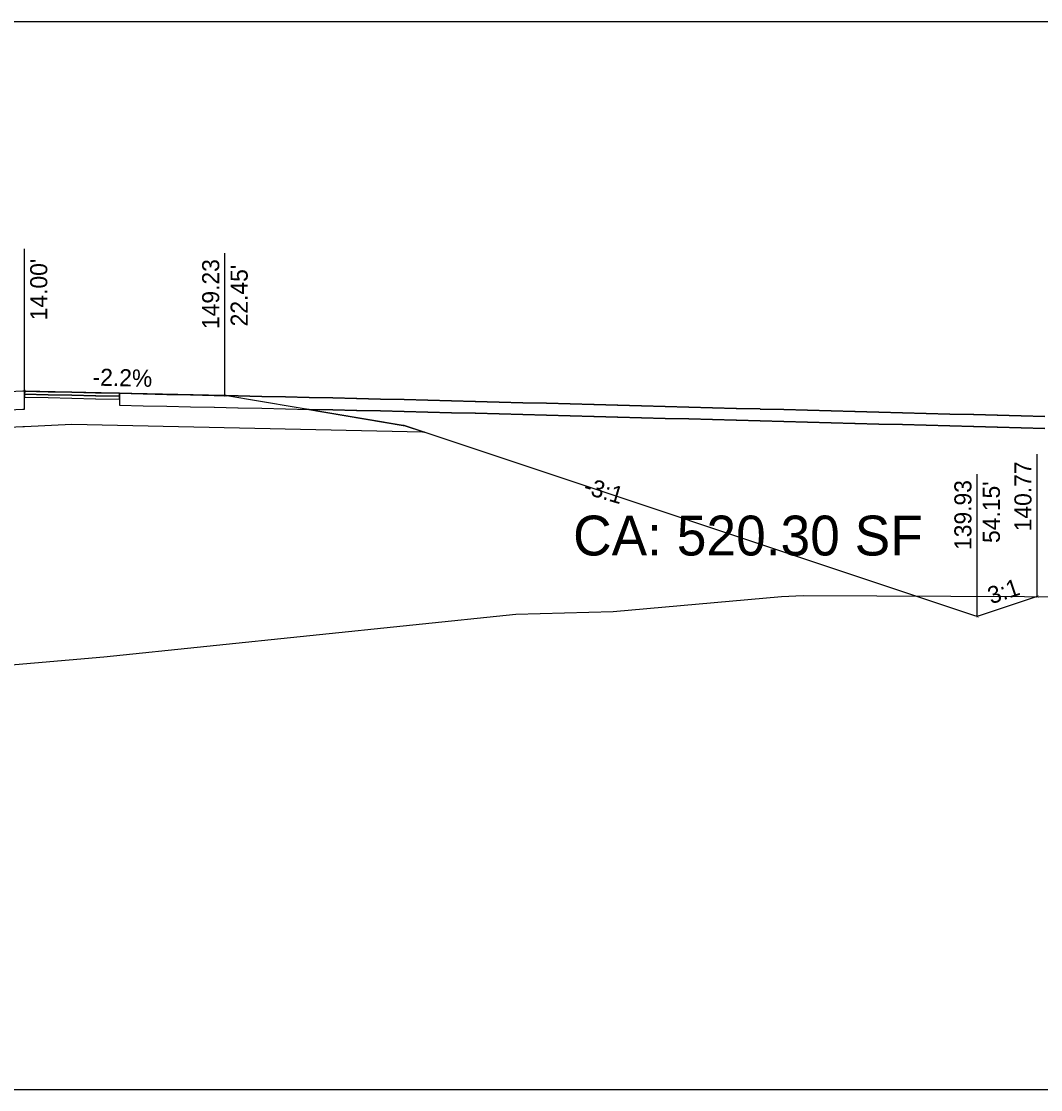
# Model space of a CAD drawing. Extents: x -26 to 4403, y -13 to 9578.
# Drawn here: x 1263.87 to 1306.82, y 7000 to 7045 of the extents above; entities that cross this region are included whole.
import ezdxf

# ---------------------------------------------------------------- set-up
doc = ezdxf.new("R2010")
doc.units = 0
for name, color, linetype in [('_CIVIL_CONSTRUCTION', 7, 'Continuous'), ('CONST_DCH', 7, 'Continuous'), ('CONST_LV3', 7, 'Continuous'), ('DTM_CORRIDOR', 7, 'Continuous'), ('DTM_P_FINISHED_GRADE', 7, 'Continuous'), ('DTM_TEMP_DROP', 7, 'Continuous'), ('DTM_X_GROUND', 7, 'Continuous'), ('XS_CELL', 7, 'Continuous'), ('XS_M_SHAPES_EARTHWORK', 7, 'Continuous'), ('XS_P_ASPHALT', 7, 'Continuous'), ('XS_P_DR_ASPHALT', 7, 'Continuous'), ('XS_P_DR_ASPHALT_B', 7, 'Continuous'), ('XS_P_DR_GRAVEL', 7, 'Continuous'), ('XS_P_GROUND', 7, 'Continuous'), ('XS_P_SHOULDER', 7, 'Continuous'), ('XS_P_SUBGRADE_GRANULAR', 7, 'Continuous'), ('XS_P_TX_CLEARZONE', 7, 'Continuous'), ('XS_P_TX_FS_BS', 7, 'Continuous'), ('XS_SHEET_EW_TX_AREA', 7, 'Continuous')]:
    doc.layers.add(name, color=color, linetype=linetype)

msp = doc.modelspace()

# ---------------------------------------------------------------- linework, layer by layer
at = {"layer": 'CONST_LV3'}
msp.add_lwpolyline([(1264, 7029.421), (1264.996, 7029.399), (1265.996, 7029.377), (1266.996, 7029.355), (1267.996, 7029.333), (1268.996, 7029.311), (1269.996, 7029.289), (1270.996, 7029.267), (1271.996, 7029.245), (1272.996, 7029.223), (1273.996, 7029.201), (1274.996, 7029.179), (1275.996, 7029.157), (1276.996, 7029.135), (1277.996, 7029.113), (1278.996, 7029.091), (1279.996, 7029.069), (1280, 7029.069), (1280.996, 7029.042), (1281.996, 7029.016), (1282.996, 7028.989), (1283.996, 7028.963), (1284.996, 7028.936), (1285.996, 7028.91), (1286.996, 7028.883), (1287.996, 7028.857), (1288.996, 7028.83), (1289.996, 7028.804), (1290.996, 7028.777), (1291.996, 7028.751), (1292.996, 7028.725), (1293.996, 7028.698), (1294.996, 7028.672), (1295.996, 7028.645), (1296.996, 7028.619), (1297.996, 7028.592), (1298.996, 7028.566), (1299.996, 7028.539), (1300.996, 7028.513), (1301.996, 7028.486), (1302.996, 7028.46), (1303.996, 7028.433), (1304.996, 7028.407), (1305.996, 7028.38), (1306.996, 7028.354)], dxfattribs=at)
at = {"layer": 'DTM_P_FINISHED_GRADE'}
for points in [[(1264, 7029.421), (1264.996, 7029.399), (1265, 7029.399), (1265.996, 7029.377), (1266, 7029.377), (1266.996, 7029.355), (1267, 7029.355), (1267.996, 7029.333), (1268, 7029.333)], [(1268, 7029.333), (1268, 7029.333), (1268.996, 7029.311), (1269, 7029.311), (1269.996, 7029.289), (1270, 7029.289), (1270.996, 7029.267), (1271, 7029.267), (1271.996, 7029.245), (1272, 7029.245), (1272.996, 7029.223), (1273, 7029.223), (1273.996, 7029.201), (1274, 7029.201), (1274.996, 7029.179), (1275, 7029.179), (1275.996, 7029.157), (1276, 7029.157), (1276.996, 7029.135), (1277, 7029.135), (1277.996, 7029.113), (1278, 7029.113), (1278.996, 7029.091), (1279, 7029.091), (1279.996, 7029.069), (1280, 7029.069), (1280.996, 7029.042), (1281, 7029.042), (1281.996, 7029.016), (1282, 7029.016), (1282.996, 7028.989), (1283, 7028.989), (1283.996, 7028.963), (1284, 7028.963), (1284.996, 7028.936), (1285, 7028.936), (1285.996, 7028.91), (1286, 7028.91), (1286.996, 7028.883), (1287, 7028.883), (1287.996, 7028.857), (1288, 7028.857), (1288.996, 7028.83), (1289, 7028.83), (1289.996, 7028.804), (1290, 7028.804), (1290.996, 7028.777), (1291, 7028.777), (1291.996, 7028.751), (1292, 7028.751), (1292.996, 7028.725), (1293, 7028.724), (1293.996, 7028.698), (1294, 7028.698), (1294.996, 7028.672), (1295, 7028.671), (1295.996, 7028.645), (1296, 7028.645), (1296.996, 7028.619), (1297, 7028.619), (1297.996, 7028.592), (1298, 7028.592), (1298.996, 7028.566), (1299, 7028.566), (1299.996, 7028.539), (1300, 7028.539), (1300.996, 7028.513), (1301, 7028.513), (1301.996, 7028.486), (1302, 7028.486), (1302.996, 7028.46), (1303, 7028.46), (1303.996, 7028.433), (1304, 7028.433), (1304.996, 7028.407), (1305, 7028.407), (1305.996, 7028.38), (1306, 7028.38), (1306.996, 7028.354)]]:
    msp.add_lwpolyline(points, dxfattribs=at)
at = {"layer": 'DTM_X_GROUND'}
msp.add_lwpolyline([(1172.393, 7016.843), (1201.803, 7015.398), (1214.564, 7014.215), (1224.971, 7013.522), (1232.816, 7013.949), (1243.916, 7015.546), (1247.514, 7017.177), (1252.067, 7016.906), (1267.338, 7018.231), (1284.701, 7020.032), (1288.812, 7020.146), (1295.897, 7020.771), (1296.81, 7020.815), (1306.145, 7020.771), (1331.242, 7020.749), (1362.053, 7020.566), (1388.429, 7020.524), (1400, 7020.43)], dxfattribs=at)
at = {"layer": 'XS_CELL'}
msp.add_line((1250, 7000), (1400, 7000), dxfattribs=at)
at = {"layer": 'XS_M_SHAPES_EARTHWORK'}
for points in [[(1306.996, 7027.854), (1306, 7027.88), (1305.996, 7027.88), (1305, 7027.907), (1304.996, 7027.907), (1304, 7027.933), (1303.996, 7027.933), (1303, 7027.96), (1302.996, 7027.96), (1302, 7027.986), (1301.996, 7027.986), (1301, 7028.013), (1300.996, 7028.013), (1300, 7028.039), (1299.996, 7028.039), (1299, 7028.066), (1298.996, 7028.066), (1298, 7028.092), (1297.996, 7028.092), (1297, 7028.119), (1296.996, 7028.119), (1296, 7028.145), (1295.996, 7028.145), (1295, 7028.171), (1294.996, 7028.172), (1294, 7028.198), (1293.996, 7028.198), (1293, 7028.224), (1292.996, 7028.225), (1292, 7028.251), (1291.996, 7028.251), (1291, 7028.277), (1290.996, 7028.277), (1290, 7028.304), (1289.996, 7028.304), (1289, 7028.33), (1288.996, 7028.33), (1288, 7028.357), (1287.996, 7028.357), (1287, 7028.383), (1286.996, 7028.383), (1286, 7028.41), (1285.996, 7028.41), (1285, 7028.436), (1284.996, 7028.436), (1284, 7028.463), (1283.996, 7028.463), (1283, 7028.489), (1282.996, 7028.489), (1282, 7028.516), (1281.996, 7028.516), (1281, 7028.542), (1280.996, 7028.542), (1280, 7028.569), (1279.996, 7028.569), (1279, 7028.591), (1278.996, 7028.591), (1278, 7028.613), (1277.996, 7028.613), (1277, 7028.635), (1276.996, 7028.635), (1276, 7028.657), (1275.996, 7028.657), (1275.901, 7028.659), (1279.961, 7027.982), (1280, 7027.976), (1280.857, 7027.69), (1280.775, 7027.692), (1266, 7028.017), (1265.989, 7028.016), (1264, 7027.921), (1263.924, 7027.917), (1250, 7027.249)], [(1252.067, 7016.906), (1267.338, 7018.231), (1284.701, 7020.032), (1288.812, 7020.146), (1295.897, 7020.771), (1296.81, 7020.815), (1306.145, 7020.771), (1331.242, 7020.749), (1362.053, 7020.566)]]:
    msp.add_lwpolyline(points, dxfattribs=at)
at = {"layer": 'XS_P_ASPHALT'}
msp.add_lwpolyline([(1249.924, 7028.745), (1236, 7028.077), (1236, 7028.073), (1236, 7027.327), (1249.924, 7027.995), (1250, 7027.999), (1263.924, 7028.667), (1264, 7028.671), (1264, 7029.417), (1264, 7029.421), (1263.924, 7029.417), (1250, 7028.749), (1249.924, 7028.745)], dxfattribs=at)
at = {"layer": 'XS_P_DR_ASPHALT'}
msp.add_lwpolyline([(1264, 7029.421), (1264, 7029.296), (1264.996, 7029.274), (1264.996, 7029.274), (1265, 7029.274), (1265.996, 7029.252), (1266, 7029.252), (1266, 7029.252), (1266, 7029.252), (1266.996, 7029.23), (1267, 7029.23), (1267.996, 7029.208), (1268, 7029.208), (1268, 7029.333), (1267.996, 7029.333), (1267, 7029.355), (1266.996, 7029.355), (1266, 7029.377), (1266, 7029.377), (1266, 7029.377), (1265.996, 7029.377), (1265, 7029.399), (1264.996, 7029.399), (1264.996, 7029.399), (1264, 7029.421)], dxfattribs=at)
at = {"layer": 'XS_P_DR_ASPHALT_B'}
msp.add_lwpolyline([(1264, 7029.296), (1264, 7029.171), (1264.996, 7029.149), (1264.996, 7029.149), (1265, 7029.149), (1265.996, 7029.127), (1266, 7029.127), (1266, 7029.127), (1266, 7029.127), (1266.996, 7029.105), (1267, 7029.105), (1267.996, 7029.083), (1268, 7029.083), (1268, 7029.208), (1267.996, 7029.208), (1267, 7029.23), (1266.996, 7029.23), (1266, 7029.252), (1266, 7029.252), (1266, 7029.252), (1265.996, 7029.252), (1265, 7029.274), (1264.996, 7029.274), (1264.996, 7029.274), (1264, 7029.296)], dxfattribs=at)
at = {"layer": 'XS_P_DR_GRAVEL'}
for points in [[(1268, 7029.333), (1268, 7028.833), (1268.996, 7028.811), (1269, 7028.811), (1269.996, 7028.789), (1269.996, 7028.789), (1270, 7028.789), (1270.996, 7028.767), (1271, 7028.767), (1271.996, 7028.745), (1272, 7028.745), (1272, 7028.745), (1272.996, 7028.723), (1273, 7028.723), (1273.996, 7028.701), (1274, 7028.701), (1274.996, 7028.679), (1275, 7028.679), (1275.996, 7028.657), (1276, 7028.657), (1276.996, 7028.635), (1277, 7028.635), (1277.996, 7028.613), (1278, 7028.613), (1278.996, 7028.591), (1279, 7028.591), (1279.996, 7028.569), (1280, 7028.569), (1280.996, 7028.542), (1281, 7028.542), (1281.996, 7028.516), (1282, 7028.516), (1282.996, 7028.489), (1283, 7028.489), (1283.996, 7028.463), (1284, 7028.463), (1284.996, 7028.436), (1285, 7028.436), (1285.996, 7028.41), (1286, 7028.41), (1286.996, 7028.383), (1287, 7028.383), (1287.996, 7028.357), (1288, 7028.357), (1288.996, 7028.33), (1289, 7028.33), (1289.996, 7028.304), (1290, 7028.304), (1290.996, 7028.277), (1291, 7028.277), (1291.996, 7028.251), (1292, 7028.251), (1292.996, 7028.225), (1293, 7028.224), (1293.996, 7028.198), (1294, 7028.198), (1294.996, 7028.172), (1295, 7028.171), (1295.996, 7028.145), (1296, 7028.145), (1296.996, 7028.119), (1297, 7028.119), (1297.996, 7028.092), (1298, 7028.092), (1298.996, 7028.066), (1299, 7028.066), (1299.996, 7028.039), (1300, 7028.039), (1300.996, 7028.013), (1301, 7028.013), (1301.996, 7027.986), (1302, 7027.986), (1302.996, 7027.96), (1303, 7027.96), (1303.996, 7027.933), (1304, 7027.933), (1304.996, 7027.907), (1305, 7027.907), (1305.996, 7027.88), (1306, 7027.88), (1306.996, 7027.854)], [(1306.996, 7028.354), (1306, 7028.38), (1305.996, 7028.38), (1305, 7028.407), (1304.996, 7028.407), (1304, 7028.433), (1303.996, 7028.433), (1303, 7028.46), (1302.996, 7028.46), (1302, 7028.486), (1301.996, 7028.486), (1301, 7028.513), (1300.996, 7028.513), (1300, 7028.539), (1299.996, 7028.539), (1299, 7028.566), (1298.996, 7028.566), (1298, 7028.592), (1297.996, 7028.592), (1297, 7028.619), (1296.996, 7028.619), (1296, 7028.645), (1295.996, 7028.645), (1295, 7028.671), (1294.996, 7028.672), (1294, 7028.698), (1293.996, 7028.698), (1293, 7028.724), (1292.996, 7028.725), (1292, 7028.751), (1291.996, 7028.751), (1291, 7028.777), (1290.996, 7028.777), (1290, 7028.804), (1289.996, 7028.804), (1289, 7028.83), (1288.996, 7028.83), (1288, 7028.857), (1287.996, 7028.857), (1287, 7028.883), (1286.996, 7028.883), (1286, 7028.91), (1285.996, 7028.91), (1285, 7028.936), (1284.996, 7028.936), (1284, 7028.963), (1283.996, 7028.963), (1283, 7028.989), (1282.996, 7028.989), (1282, 7029.016), (1281.996, 7029.016), (1281, 7029.042), (1280.996, 7029.042), (1280, 7029.069), (1279.996, 7029.069), (1279, 7029.091), (1278.996, 7029.091), (1278, 7029.113), (1277.996, 7029.113), (1277, 7029.135), (1276.996, 7029.135), (1276, 7029.157), (1275.996, 7029.157), (1275, 7029.179), (1274.996, 7029.179), (1274, 7029.201), (1273.996, 7029.201), (1273, 7029.223), (1272.996, 7029.223), (1272, 7029.245), (1272, 7029.245), (1271.996, 7029.245), (1271, 7029.267), (1270.996, 7029.267), (1270, 7029.289), (1269.996, 7029.289), (1269.996, 7029.289), (1269, 7029.311), (1268.996, 7029.311), (1268, 7029.333)]]:
    msp.add_lwpolyline(points, dxfattribs=at)
at = {"layer": 'XS_P_GROUND'}
msp.add_line((1250, 7045), (1380, 7045), dxfattribs=at)
for points in [[(1304.145, 7019.928), (1304.012, 7019.972), (1280, 7027.976), (1279.961, 7027.982), (1272.446, 7029.235)], [(1306.675, 7020.771), (1304.145, 7019.928)]]:
    msp.add_lwpolyline(points, dxfattribs=at)
at = {"layer": 'XS_P_SHOULDER'}
msp.add_lwpolyline([(1272.446, 7029.235), (1272.398, 7029.236), (1264, 7029.421)], dxfattribs=at)
at = {"layer": 'XS_P_SUBGRADE_GRANULAR'}
for points in [[(1264, 7027.921), (1263.924, 7027.917), (1250, 7027.249)], [(1280.857, 7027.69), (1280.775, 7027.692), (1266, 7028.017), (1265.989, 7028.016), (1264, 7027.921)]]:
    msp.add_lwpolyline(points, dxfattribs=at)
at = {"layer": 'XS_P_TX_CLEARZONE'}
for p, q in [((1264, 7029.421), (1264, 7035.421)), ((1264, 7029.421), (1264, 7035.421)), ((1264, 7029.421), (1264, 7035.421)), ((1264, 7029.421), (1264, 7035.421)), ((1264, 7029.421), (1264, 7035.421)), ((1264, 7029.421), (1264, 7035.421)), ((1272.446, 7029.235), (1272.446, 7035.235)), ((1272.446, 7029.235), (1272.446, 7035.235)), ((1272.446, 7029.235), (1272.446, 7035.235)), ((1272.446, 7029.235), (1272.446, 7035.235)), ((1272.446, 7029.235), (1272.446, 7035.235)), ((1272.446, 7029.235), (1272.446, 7035.235)), ((1306.675, 7020.771), (1306.675, 7026.771)), ((1306.675, 7020.771), (1306.675, 7026.771)), ((1306.675, 7020.771), (1306.675, 7026.771)), ((1304.145, 7019.928), (1304.145, 7025.928)), ((1304.145, 7019.928), (1304.145, 7025.928)), ((1304.145, 7019.928), (1304.145, 7025.928))]:
    msp.add_line(p, q, dxfattribs=at)

# ---------------------------------------------------------------- texts
at = {"layer": '_CIVIL_CONSTRUCTION'}
msp.add_text('X', height=0.12, dxfattribs=at).set_placement((1263.961, 7029.361))
at = {"layer": 'CONST_DCH'}
msp.add_text('X', height=0.12, dxfattribs=at).set_placement((1304.106, 7019.868))
at = {"layer": 'DTM_CORRIDOR'}
msp.add_text('X', height=0.12, dxfattribs=at).set_placement((1306.635, 7020.711))
at = {"layer": 'DTM_TEMP_DROP'}
msp.add_text('X', height=0.12, dxfattribs=at).set_placement((1272.406, 7029.175))
at = {"layer": 'XS_P_TX_CLEARZONE'}
for s, p in [("14.00'", (1264.96, 7032.406)), ("14.00'", (1264.96, 7032.406)), ("14.00'", (1264.96, 7032.406)), ("14.00'", (1264.96, 7032.406)), ("14.00'", (1264.96, 7032.406)), ("14.00'", (1264.96, 7032.406)), ('149.23', (1272.206, 7032.039)), ('149.23', (1272.206, 7032.039)), ('149.23', (1272.206, 7032.039)), ('149.23', (1272.206, 7032.039)), ('149.23', (1272.206, 7032.039)), ('149.23', (1272.206, 7032.039)), ("22.45'", (1273.406, 7032.152)), ("22.45'", (1273.406, 7032.152)), ("22.45'", (1273.406, 7032.152)), ("22.45'", (1273.406, 7032.152)), ("22.45'", (1273.406, 7032.152)), ("22.45'", (1273.406, 7032.152)), ('140.77', (1306.435, 7023.518)), ('140.77', (1306.435, 7023.518)), ('140.77', (1306.435, 7023.518)), ('139.93', (1303.905, 7022.732)), ('139.93', (1303.905, 7022.732)), ('139.93', (1303.905, 7022.732)), ("54.15'", (1305.105, 7023.027)), ("54.15'", (1305.105, 7023.027)), ("54.15'", (1305.105, 7023.027))]:
    msp.add_text(s, height=0.72, rotation=90, dxfattribs=at).set_placement(p)
at = {"layer": 'XS_P_TX_FS_BS'}
for s, rotation, p in [('-2.2%', 358.7397, (1266.861, 7029.658)), ('-2.2%', 358.7397, (1266.861, 7029.658)), ('-2.2%', 358.7397, (1266.861, 7029.658)), ('-3:1', 343.6379, (1287.51, 7025.125)), ('-3:1', 343.6379, (1287.51, 7025.125)), ('-3:1', 343.6379, (1287.51, 7025.125)), ('3:1', 18.4349, (1304.734, 7020.44)), ('3:1', 18.4349, (1304.734, 7020.44)), ('3:1', 18.4349, (1304.734, 7020.44))]:
    msp.add_text(s, height=0.72, rotation=rotation, dxfattribs=at).set_placement(p)
at = {"layer": 'XS_SHEET_EW_TX_AREA'}
msp.add_text('CA: 520.30 SF', height=1.68, dxfattribs=at).set_placement((1287.119, 7022.5))

doc.saveas('drawing.dxf')
